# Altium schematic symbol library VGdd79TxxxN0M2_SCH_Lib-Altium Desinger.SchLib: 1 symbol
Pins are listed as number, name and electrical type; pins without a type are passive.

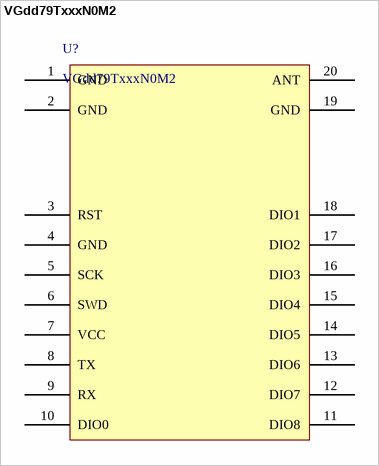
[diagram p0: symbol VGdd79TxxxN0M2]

## VGdd79TxxxN0M2
designator U?
pins: 1 GND, 2 GND, 3 RST, 4 GND, 5 SCK, 6 SWD, 7 VCC, 8 TX, 9 RX, 10 DIO0, 11 DIO8, 12 DIO7, 13 DIO6, 14 DIO5, 15 DIO4, 16 DIO3, 17 DIO2, 18 DIO1, 19 GND, 20 ANT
